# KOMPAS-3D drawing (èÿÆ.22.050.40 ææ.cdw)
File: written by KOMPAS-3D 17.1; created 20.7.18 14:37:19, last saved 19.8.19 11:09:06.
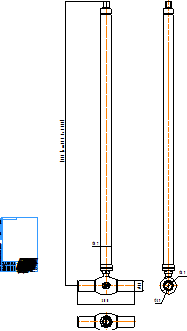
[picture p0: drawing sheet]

Sheet 1: A4, portrait

Title block, sheet 1: name: КШТ.22.050.40 С/С; sheets: 1; sheet format: A4; stored path: C:\Users\kka\KOMPAS_Work\Модели кранов для исследований\DN50\С удлинением\КШТ.22.050.40 СС.cdw

Views: Вид 1, Спереди
Referenced files in C:\Users\kka\KOMPAS_Work\Модели кранов для исследований\DN32\С удлинением\: КШГ.32.032.40 СС.a3d
Referenced files in C:\Users\kka\KOMPAS_Work\Модели кранов для исследований\DN50\С удлинением\: КШТ.22.050.40 СС.a3d, КШТ.22.050.40 СС.a3d!Деталь (локальная).m3d
Referenced files in C:\Users\kka\KOMPAS_Work\Модели кранов для исследований\DN50\: АПТА.0203-1704.04.01 _ Корпус крана Ду50 (Труба по ГОСТ).m3d, АПТА.0203-2615.11.01 _ Шар Ду50.m3d, АПТА.0203-2613.11.01 _ Шток Ду40-50.m3d, АПТА.0203-2613.12.01 _ Корпус штока Ду40-50.m3d, АПТА.0203-2613.11.06 _ Кольцо прокладочное Ду40-50.m3d, АПТА.0203-2613.11.05 _ Шайба штока Ду40-50.m3d, АПТА.0203-2613.11.03 _ Шайба фрикционная Ду40-50.m3d, АПТА.0203-2613.11.04 _ Подкладка для кольца Ду40-50.m3d, Кольцо EPDM 14.3x2.4.m3d, Кольцо Viton 14.3x2.4.m3d, АПТА.0203-1704.00.00 _ Кран шаровой сварной Ду50 (труба по ГОСТ).a3d!АПТА.0203-1704.00.00!Деталь (локальная).m3d, СедлоДу50.m3d, Кольцо+опорное_Ду50.m3d, АПТА.0203-1704.03.01 _ Патрубок сварной точенный Ду50 (труба по ГОСТ).m3d, АПТА.0203-2615.02.02 _ Кольцо горловое Ду50.m3d, АПТА.0203-1704.00.00 _ Кран шаровой сварной Ду50 (труба по ГОСТ).a3d!АПТА.0203-1704.00.00!Деталь (локальная) 1.m3d, АПТА.0203-2615.02.03 _ Пружина тарельчатая Ду50.m3d, АПТА.0203-1704.00.00 _ Кран шаровой сварной Ду50 (труба по ГОСТ).a3d
Referenced files in C:\Program Files\ASCON\KOMPAS-3D v17\Libs\PartLib\DATA\VAULT\methods\kompas\3d\: PLib_Parallel_Pin_ISO_1100.m3d, PLib_Blind_Nut_type1_900.m3d, PLib_Check_spring_rings_GOST_13942_911.m3d, PLib_Pin_3128_712.m3d, PLib_Bolt_1_900.m3d, PLib_Washer_2_712.m3d
Referenced files in C:\Users\kka\KOMPAS_Work\КШ удлиненные ПП МОСФЛОУЛАЙН ф. ADL\DN32ПП\: АПТА.0203-2613.03.02 _ Ухватка Ду40-50.m3d, АПТА.0203-2613.03.01 _ Рукоятка Ду40-50.m3d, АПТА.0203-2613.03.00 _ Ручка Ду40-50.a3d
Referenced files in C:\Users\kka\KOMPAS_Work\Удлинения БИВАЛ ф. ADL\Небюджет\Специальные ISO фланцы\: Фланец Ду40-50.m3d
Referenced files in C:\Users\kka\KOMPAS_Work\!Trash\Электроприводы\: SQ05.2.m3d, SG 04.3-F07.m3d
Referenced files in C:\Users\kka\KOMPAS_Work\Удлинения БИВАЛ ф. ADL\Небюджет\Удлинения_2010\УШДн40-50\: УШ.261.00.03 _ Фланец нижний Ду20-50.m3d, УШ.251.00.07 _ Прокладка Ду20-50.m3d, УШ.261.01.01 _ Головка штока Ду20-80.m3d, УШ.266.01.02 _ Адаптер Ду40-50.m3d, УШ.266.00.00 _ Удлинение штока Ду40-50.a3d!УШ.266.00.00!Деталь (локальная).m3d, УШ.261.00.05 _ Крышка корпуса Ду20-80.m3d, УШ.261.00.06 _ Кольцо запорное Ду20-150.m3d, УШ.266.00.00 _ Удлинение штока Ду40-50.a3d!УШ.266.00.00!Деталь (локальная) 1.m3d, УШ.266.00.00 _ Удлинение штока Ду40-50.a3d
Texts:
  kka
  adl
  (от 250 до 5000)
  Рама для чертежей
  Лит-Масса-Масштаб
  Материал-Предприятие
  Масштаб
  Изм.
  Лист
  № докум.
  Подп.
  Дата
  Лит.
  Разраб.
  Пров.
  Т.контр.
  Листов
  Внимание! Данный продукт является объектом авторского права ООО «Торговый Дом АДЛ».
  Запрещается изменение, копирование, распространение
  (в том числе путем копирования на другие сайты и ресурсы в Интернете)
  или любое иное использование информации и объектов без предварительного
  согласия правообладателя (ООО «Торговый Дом АДЛ»).
  Н.контр.
  Утв.
  ООО "Торговый дом АДЛ"
  Изменение
  Номер документа
  Подпись
  Обозначение документа
  Наименование изделия
  Масса изделия по ГОСТ 2.109-73
  Порядковый номер листа
  Общее количество листов в документе
  Характер работы, выполненной лицом, подписавшим документ
  Наименование или индекс предприятия, выпускающего документ
  Инв. № подл.
  Подп. и дата
  Взам. инв. №
  Инв. № дубл.
  Инвентарный номер подлинника по ГОСТ 2.501-68
  Подпись принявшего подлинник в отдел технической документации
  Инвентарный номер подлинника, взамен которого выпущен данный подлинник
  Инвентарный номер дубликата по ГОСТ 2.502-68
  Подпись принявшего дубликат в отдел технической документации
  Справ. №
  Перв. примен.
  Обозначение документа, взамен или на основании которого выпущен данный документ
  Обозначение документа, в котором впервые записан данный документ
  Подпись лица, копировавшего чертеж
  Обозначение формата листа
  !Рама для чертежа
  Корпус крана Ду50 (Труба по ГОСТ)
  АПТА.0203-1704.04.01
  Шар Ду50
  АПТА.0203-2615.11.01
  Шток Ду40-50
  АПТА.0203-2613.11.01
  Корпус штока Ду40-50
  АПТА.0203-2613.12.01
  Кольцо прокладочное Ду40-50
  АПТА.0203-2613.11.06
  Шайба штока Ду40-50
  АПТА.0203-2613.11.05
  Шайба фрикционная Ду40-50
  АПТА.0203-2613.11.03
  Подкладка для кольца Ду40-50
  АПТА.0203-2613.11.04
  Кольцо EPDM 14.3x2.4
  Кольцо Viton 14.3x2.4
  Parallel pin ISO 2338 - 4 h8 x 28 - A1
  Деталь (локальная)
  Седловое уплотнение Ду50
  АПТА.0203-2615.02.05
  Кольцо опорное Ду50
  АПТА.0203-2615.02.04
  Патрубок сварной точенный Ду50 (труба по ГОСТ)
  АПТА.0203-1704.03.01
  Кольцо горловое Ду50
  АПТА.0203-2615.02.02
  Ухватка Ду40-50
  АПТА.0203-2613.03.02
  Рукоятка Ду40-50
  АПТА.0203-2613.03.01
  Ручка Ду40-50
  АПТА.0203-2613.03.00
  Гайка М14-6H ГОСТ 11860-85
  Пружина тарельчатая Ду50
  АПТА.0203-2615.02.03
  Фланец для присоединения  приводов Ду 40-50
  ФС.4050.00.01
  SQ05.2 220В
  Кран шаровой сварной Ду50 (труба по ГОСТ)
  АПТА.0203-1704.00.00
  Фланец нижний Ду20-50
  УШ.261.00.03
  Прокладка Ду20-50
  УШ.251.00.07
  Головка штока Ду20-80
  УШ.261.01.01
  Адаптер Ду40-50
  УШ.266.01.02
  Удлинитель
  Крышка корпуса Ду20-80
  УШ.261.00.05
  Кольцо A36.65 ГОСТ 13942-86
  Кольцо запорное Ду20-150
  УШ.261.00.06
  Корпус
  Штифт 2.8x16 ГОСТ 3128-70
  Штифт 2.10x45 ГОСТ 3128-70
  Болт М6-6gx25.68.019 ГОСТ 7805-70
  Шайба 6 65Г 019 ГОСТ 6402-70
  Удлинение штока Ду40-50
  УШ.266.00.00
Dimensions and other numbers on the sheet: 300; 57; 1500; 1:1; 1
